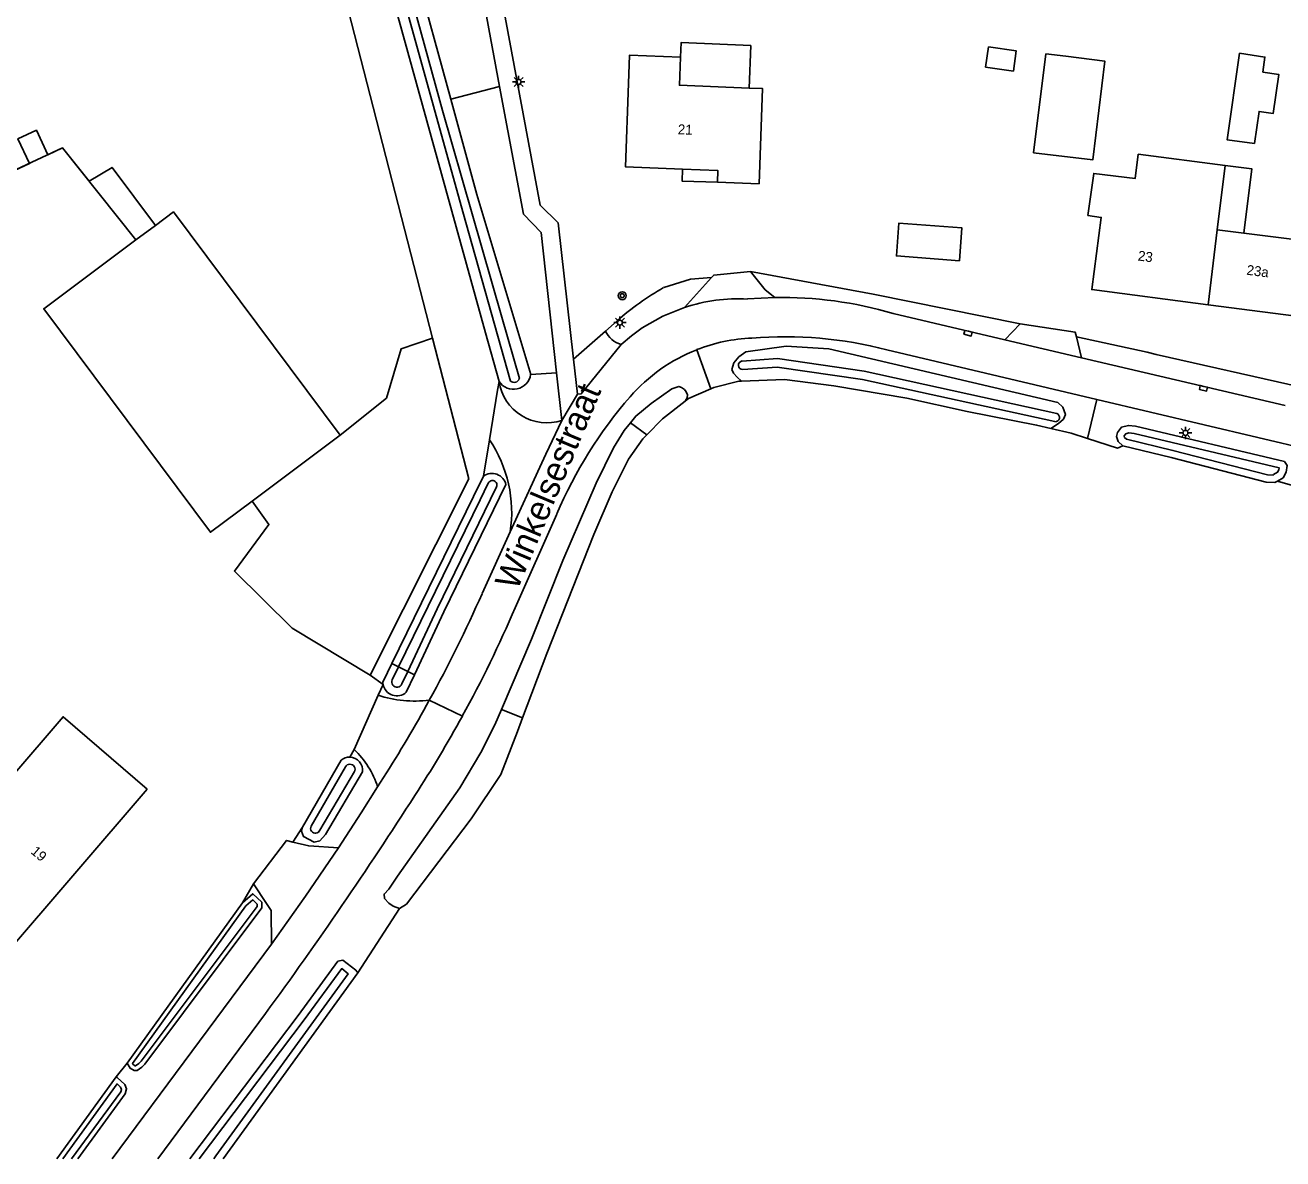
# Model space of a CAD drawing. Extents: x 140000 to 143000, y 403500 to 406000.
# Drawn here: x 140373.2 to 140499.7, y 403500 to 403614.1 of the extents above; entities that cross this region are included whole.
import ezdxf

# ---------------------------------------------------------------- set-up
doc = ezdxf.new("R2010")
doc.units = 0
for name, color, linetype in [('gg-afsc-erfafscheiding', 7, 'Continuous'), ('gg-afsc-hekwerk', 7, 'Continuous'), ('gg-anno-huisnummerreeks BGT', 7, 'Continuous'), ('gg-anno-openbare ruimte label', 7, 'Continuous'), ('gg-bbg-bijgebouw', 7, 'Continuous'), ('gg-bbg-hoofdgebouw', 7, 'Continuous'), ('gg-bbg-luifel en loopbrug', 7, 'Continuous'), ('gg-bbg-overig bouwwerk', 7, 'Continuous'), ('gg-bbg-tussenscheiding', 7, 'Continuous'), ('gg-knt-bronhoudergrens', 7, 'Continuous'), ('gg-knt-verharding', 7, 'Continuous'), ('gg-knt-verharding nz', 7, 'Continuous'), ('gg-kntw-bovenkant insteek waterloop', 7, 'Continuous'), ('gg-kntw-waterlijn', 7, 'Continuous'), ('gt-grn-groengrens', 7, 'Continuous'), ('gt-grn-groengrens NZ', 7, 'Continuous'), ('gt-grn-vlakafsluiter', 7, 'Continuous'), ('gt-grn-weggrens', 7, 'Continuous'), ('gt-symb-boom', 7, 'Continuous'), ('gt-symb-kolk', 7, 'Continuous'), ('gt-symb-lichtmast', 7, 'Continuous')]:
    doc.layers.add(name, color=color, linetype=linetype)

# ---------------------------------------------------------------- blocks, each defined once
blk = doc.blocks.new('gt0-LMAST')
at = {"layer": 'gt-symb-lichtmast'}
for p, q in [((-0.18, 0.17), (-0.45, 0.44)), ((-0.01, 0.25), (-0.01, 0.62)), ((0.17, 0.17), (0.44, 0.44)), ((-0.26, 0), (-0.63, 0)), ((-0.18, -0.18), (-0.45, -0.45)), ((-0.01, -0.25), (-0.01, -0.63)), ((0.44, -0.45), (0.17, -0.18)), ((0.24, 0), (0.62, 0))]:
    blk.add_line(p, q, dxfattribs=at)
blk.add_circle((-0.01, 0), 0.25, dxfattribs=at)
blk = doc.blocks.new('gt0-KOLK')
at = {"layer": 'gt-symb-kolk'}
blk.add_lwpolyline([(0, 0), (0.38, 0), (0.38, 0.4), (-0.37, 0.4), (-0.37, 0), (0, 0)], dxfattribs=at)
blk = doc.blocks.new('gt0-BOOM')
at = {"layer": 'gt-symb-boom'}
for radius in [0.4, 0.2]:
    blk.add_circle((0, 0), radius, dxfattribs=at)

msp = doc.modelspace()

# ---------------------------------------------------------------- linework, layer by layer
at = {"layer": 'gg-afsc-erfafscheiding'}
for p, q in [((140431.56, 403583.29), (140432.73, 403584.31)), ((140407.9, 403548.67), (140409.2, 403547.73)), ((140409.2, 403547.73), (140408.68, 403546.64)), ((140406.26, 403541.18), (140405.83, 403540.42)), ((140401.07, 403533.39), (140400.11, 403531.88)), ((140396.14, 403527.66), (140395.04, 403525.77)), ((140383.43, 403509.63), (140382.34, 403508.24))]:
    msp.add_line(p, q, dxfattribs=at)
for points in [[(140442.22, 403588.68), (140440.1, 403588.52), (140437.41, 403587.66)], [(140446.16, 403589.28), (140458.47, 403587.02), (140473.26, 403584.03)], [(140501.53, 403577.66), (140486.94, 403580.93), (140486.06, 403581.18), (140478.93, 403582.72)]]:
    msp.add_lwpolyline(points, dxfattribs=at)
msp.add_arc((140450.92, 403563.83), 27.4, 119.5448, 131.6023, dxfattribs=at)
at = {"layer": 'gg-afsc-hekwerk'}
msp.add_line((140483.05, 403571.5), (140480.06, 403572.48), dxfattribs=at)
for points in [[(140384.32, 403592.47), (140376.95, 403601.73), (140355.11, 403591.55), (140356.27, 403589.35)], [(140414.17, 403582.59), (140410.99, 403581.49), (140409.52, 403576.55), (140404.88, 403572.81)], [(140407.9, 403548.67), (140417.82, 403568.41), (140414.17, 403582.59)], [(140442.16, 403577.49), (140439.9, 403576.5), (140439.57, 403576.24)], [(140445.23, 403578.25), (140444.96, 403578.24), (140442.44, 403577.61), (140442.16, 403577.49)], [(140476.36, 403573.5), (140474.92, 403573.84), (140467.95, 403575.21), (140461.87, 403576.54), (140454.52, 403577.79), (140449.57, 403578.43), (140445.23, 403578.25)], [(140439.57, 403576.24), (140437.3, 403574.46), (140435.7, 403572.84), (140435.33, 403572.46), (140433.86, 403570.39), (140432.24, 403567.1), (140430.39, 403562.83), (140425.66, 403550.86), (140423.21, 403544.36), (140422.7, 403543.01)], [(140480.06, 403572.48), (140478.4, 403573.03), (140476.36, 403573.5)], [(140396.01, 403566.18), (140397.7, 403563.83), (140394.22, 403559.14), (140400.05, 403553.4), (140407.9, 403548.67)]]:
    msp.add_lwpolyline(points, dxfattribs=at)
at = {"layer": 'gg-bbg-bijgebouw'}
for p, q in [((140386.28, 403593.93), (140384.32, 403592.47)), ((140396.01, 403566.18), (140404.88, 403572.81))]:
    msp.add_line(p, q, dxfattribs=at)
for points in [[(140475.84, 403611.19), (140474.62, 403601.24), (140480.58, 403600.52), (140481.78, 403610.46), (140477.85, 403610.95), (140475.84, 403611.19)], [(140404.88, 403572.81), (140388.1, 403595.29), (140386.28, 403593.93)], [(140384.32, 403592.47), (140375.04, 403585.54), (140391.82, 403563.05), (140396.01, 403566.18)]]:
    msp.add_lwpolyline(points, dxfattribs=at)
at = {"layer": 'gg-bbg-hoofdgebouw'}
for q in [(140493.88, 403599.96), (140495.76, 403593.14)]:
    msp.add_line((140493.08, 403593.47), q, dxfattribs=at)
for points in [[(140439.11, 403610.86), (140433.96, 403611.05), (140433.86, 403608.21), (140433.57, 403599.81), (140439.31, 403599.58)], [(140446.01, 403607.75), (140438.99, 403608.02), (140439.11, 403610.86)], [(140446.01, 403607.75), (140447.36, 403607.7), (140447.01, 403598.11), (140442.81, 403598.26)], [(140493.88, 403599.96), (140485.15, 403601.08), (140484.83, 403598.64), (140480.68, 403599.15), (140480.09, 403594.93), (140481.42, 403594.73), (140480.47, 403587.47), (140492.18, 403585.94)], [(140439.31, 403599.58), (140442.86, 403599.44), (140442.81, 403598.26)], [(140492.18, 403585.94), (140503.1, 403584.51), (140504.08, 403592.11), (140495.76, 403593.14)], [(140385.46, 403537.21), (140376.99, 403544.49), (140366.44, 403532.19), (140368.31, 403530.59), (140364.3, 403525.91), (140367.1, 403523.5), (140370.89, 403520.24), (140385.46, 403537.21)]]:
    msp.add_lwpolyline(points, dxfattribs=at)
at = {"layer": 'gg-bbg-luifel en loopbrug'}
for points in [[(140446.01, 403607.75), (140446.17, 403612.02), (140439.18, 403612.33), (140439.11, 403610.86)], [(140493.88, 403599.96), (140496.56, 403599.62), (140495.76, 403593.14)], [(140439.31, 403599.58), (140439.26, 403598.39), (140442.81, 403598.26)]]:
    msp.add_lwpolyline(points, dxfattribs=at)
at = {"layer": 'gg-bbg-overig bouwwerk'}
for points in [[(140469.8, 403609.85), (140472.59, 403609.45), (140472.88, 403611.48), (140470.09, 403611.88), (140469.8, 403609.85)], [(140495.34, 403611.26), (140494.1, 403602.52), (140496.84, 403602.17), (140497.3, 403605.39), (140498.71, 403605.18), (140499.28, 403609.12), (140497.69, 403609.35), (140497.89, 403610.86), (140495.34, 403611.26)], [(140467.17, 403590.37), (140467.42, 403593.67), (140461.08, 403594.15), (140460.83, 403590.85), (140467.17, 403590.37)]]:
    msp.add_lwpolyline(points, dxfattribs=at)
at = {"layer": 'gg-bbg-tussenscheiding'}
msp.add_line((140492.18, 403585.94), (140493.08, 403593.47), dxfattribs=at)
at = {"layer": 'gg-knt-bronhoudergrens'}
for p, q in [((140502.08, 403567.36), (140499.15, 403568.2)), ((140406.65, 403518.71), (140410.83, 403525.18))]:
    msp.add_line(p, q, dxfattribs=at)
for points in [[(140356.27, 403589.35), (140355.11, 403591.55), (140373.6, 403600.17), (140372.45, 403602.64), (140374.31, 403603.5), (140375.46, 403601.04), (140376.95, 403601.73), (140379.63, 403598.36), (140381.93, 403599.76), (140386.28, 403593.93)], [(140439.57, 403576.24), (140439.9, 403576.5), (140442.16, 403577.49)], [(140442.16, 403577.49), (140442.44, 403577.61), (140444.96, 403578.24), (140445.23, 403578.25)], [(140480.06, 403572.48), (140478.4, 403573.03), (140476.36, 403573.5)], [(140480.06, 403572.48), (140483.05, 403571.5), (140483.59, 403571.74)]]:
    msp.add_lwpolyline(points, dxfattribs=at)
at = {"layer": 'gg-knt-verharding'}
for p, q in [((140439.51, 403585.68), (140442.22, 403588.68)), ((140471.74, 403582.42), (140460.49, 403585.05)), ((140471.74, 403582.42), (140473.26, 403584.03)), ((140428.35, 403580.45), (140431.56, 403583.29)), ((140479.44, 403580.61), (140478.93, 403582.72)), ((140459.86, 403581.41), (140480.99, 403576.41)), ((140428.75, 403576.95), (140428.35, 403580.45)), ((140499.92, 403575.82), (140479.44, 403580.61)), ((140427.17, 403574.3), (140426.64, 403579.09)), ((140428.75, 403576.95), (140427.17, 403574.3)), ((140480.99, 403576.41), (140502.99, 403571.2)), ((140422.48, 403555.45), (140426.67, 403564.88)), ((140421.98, 403563.08), (140419.14, 403556.87)), ((140406.26, 403541.18), (140408.68, 403546.64)), ((140381.93, 403500), (140397.96, 403521.61)), ((140386.52, 403500), (140397.34, 403514.62))]:
    msp.add_line(p, q, dxfattribs=at)
for points in [[(140406.1, 403674.88), (140407.67, 403655.99), (140419.56, 403619.22), (140419.42, 403615.9), (140420.91, 403607.91)], [(140428.35, 403580.45), (140426.79, 403594.18), (140424.99, 403595.96), (140421.18, 403616.33), (140421.45, 403619.53), (140409.47, 403656.48), (140408.2, 403671.5), (140411.12, 403673.65), (140421.06, 403674.9)], [(140420.91, 403607.91), (140423.3, 403595.07), (140425.07, 403593.22), (140426.64, 403579.09)], [(140446.16, 403589.28), (140442.44, 403588.92), (140442.22, 403588.68)], [(140448.58, 403586.67), (140447.62, 403587.43), (140446.16, 403589.28)], [(140439.51, 403585.68), (140437.31, 403584.8), (140435.26, 403583.62), (140434.16, 403582.83), (140433.13, 403581.95)], [(140473.26, 403584.03), (140478.81, 403583.17), (140478.93, 403582.72)], [(140419.89, 403572.36), (140420.71, 403577.33), (140420.85, 403578.21)], [(140407.9, 403548.67), (140400.05, 403553.4), (140394.22, 403559.14), (140397.7, 403563.83), (140396.01, 403566.18)], [(140408.63, 403537.42), (140406.99, 403534.82), (140404.69, 403531.31)], [(140400.11, 403531.88), (140399.47, 403532.04), (140396.14, 403527.66)], [(140404.69, 403531.31), (140401.7, 403531.48), (140400.11, 403531.88)], [(140397.96, 403521.61), (140397.92, 403524.99), (140397.44, 403525.71), (140396.14, 403527.66)]]:
    msp.add_lwpolyline(points, dxfattribs=at)
for centre, radius, start, end in [((140449.34, 403547.61), 39.07, 73.4147, 91.1163), ((140433.86, 403584.4), 2.56, 205.8661, 253.354), ((140446.97, 403565.5), 17.1, 92.2921, 111.3633), ((140449.59, 403541.58), 41.14, 75.5411, 94.6075), ((140446.97, 403565.5), 17.09, 111.3791, 139.1474), ((140425.66, 403578.92), 4.86, 188.4604, 288.1012), ((140467.62, 403547.51), 44.49, 139.0139, 157.0076), ((140409, 403565.03), 13.12, 351.4562, 33.9414), ((140290.11, 403614.04), 141.13, 331.2439, 336.1015), ((140309.19, 403603.93), 123.22, 331.1874, 336.8348), ((140412.36, 403557.97), 11.91, 251.9994, 277.0863), ((140309.2, 403603.91), 123.21, 326.873, 331.1932), ((140400.51, 403534.92), 8.5, 17.0887, 47.4029), ((140049.51, 403769.07), 430.97, 323.8141, 327.3521)]:
    msp.add_arc(centre, radius, start, end, dxfattribs=at)
at = {"layer": 'gg-knt-verharding nz'}
for p, q in [((140479.44, 403580.61), (140471.74, 403582.42)), ((140409.24, 403538.37), (140408.63, 403537.42))]:
    msp.add_line(p, q, dxfattribs=at)
for points in [[(140448.58, 403586.67), (140447.21, 403586.62), (140445.85, 403586.52)], [(140433.13, 403581.95), (140429.11, 403576.99), (140428.75, 403576.95)], [(140427.17, 403574.3), (140425.55, 403570.92), (140424.95, 403569.6), (140421.98, 403563.08)], [(140404.69, 403531.31), (140401.37, 403526.42), (140397.96, 403521.61)]]:
    msp.add_lwpolyline(points, dxfattribs=at)
for centre, radius, start, end in [((140444.92, 403569.13), 17.41, 86.9418, 108.1018), ((140289.84, 403614.18), 141.43, 327.5859, 331.2477)]:
    msp.add_arc(centre, radius, start, end, dxfattribs=at)
at = {"layer": 'gg-kntw-bovenkant insteek waterloop'}
for p, q in [((140410.07, 403549.85), (140409.18, 403548.03)), ((140411.51, 403546.95), (140412.33, 403548.7)), ((140401.07, 403533.39), (140404.96, 403540.12)), ((140395.04, 403525.77), (140383.43, 403509.63)), ((140393.09, 403500), (140406.65, 403518.71)), ((140376.37, 403500), (140382.34, 403508.24))]:
    msp.add_line(p, q, dxfattribs=at)
for points in [[(140420.85, 403578.21), (140419.47, 403583.11), (140410.65, 403615.1), (140404.44, 403637.32), (140400.95, 403650.31), (140399.75, 403655.87), (140397.36, 403674.15), (140397.48, 403675.34), (140397.93, 403676.05), (140398.38, 403676.52), (140398.92, 403676.79), (140399.36, 403676.66), (140399.71, 403676.32), (140402.3, 403656.1), (140403.18, 403651.75), (140408.57, 403633.77), (140416, 403606.64)], [(140416, 403606.64), (140418.63, 403597.03), (140424.03, 403578.92)], [(140445.23, 403578.25), (140444.79, 403578.65), (140444.45, 403579.04), (140444.27, 403579.42), (140444.46, 403580.1), (140444.96, 403580.69), (140445.66, 403581.22), (140449.74, 403581.79), (140454.01, 403581.52), (140477.05, 403576.12), (140477.57, 403575.62), (140477.82, 403574.91), (140477.63, 403574.43), (140477.13, 403573.98), (140476.36, 403573.5)], [(140439.57, 403576.24), (140439.77, 403576.59), (140439.8, 403576.89), (140439.67, 403577.17), (140439.49, 403577.41), (140439.2, 403577.61), (140438.93, 403577.72), (140438.22, 403577.48), (140436.14, 403575.99), (140434.6, 403574.73), (140434.06, 403574.07)], [(140445.23, 403578.25), (140449.57, 403578.43), (140454.52, 403577.79), (140461.87, 403576.54), (140467.95, 403575.21), (140474.92, 403573.84), (140476.36, 403573.5)], [(140439.57, 403576.24), (140437.3, 403574.46), (140435.7, 403572.84)], [(140434.06, 403574.07), (140433.44, 403573.3), (140432.35, 403571.54), (140430.63, 403567.98), (140427.26, 403560.2), (140424.11, 403552.29), (140421.09, 403545.23)], [(140483.59, 403571.74), (140483.14, 403572.17), (140482.95, 403572.67), (140483.05, 403573.09), (140483.45, 403573.62), (140484.16, 403573.8), (140484.88, 403573.71), (140499.85, 403570.17), (140500.13, 403569.78), (140500.02, 403569.09), (140499.73, 403568.54), (140499.15, 403568.2)], [(140435.7, 403572.84), (140435.33, 403572.46), (140433.86, 403570.39), (140432.24, 403567.1), (140430.39, 403562.83), (140425.66, 403550.86), (140423.21, 403544.36)], [(140483.59, 403571.74), (140488.46, 403570.56), (140498.03, 403568.09), (140498.9, 403568.06), (140499.15, 403568.2)], [(140410.07, 403549.85), (140418.28, 403566.63), (140419.28, 403568.68)], [(140412.33, 403548.7), (140415.29, 403555.04), (140421.54, 403567.84)], [(140421.09, 403545.23), (140420.42, 403543.68), (140419.02, 403540.88), (140416.89, 403537.32), (140410.62, 403528.45), (140409.76, 403527.13), (140409.29, 403526.64), (140409.34, 403526.2), (140409.76, 403525.73), (140410.21, 403525.44), (140410.83, 403525.18)], [(140423.21, 403544.36), (140422.7, 403543.01), (140421.02, 403538.67), (140418.05, 403534.22), (140411.54, 403525.64), (140410.83, 403525.18)], [(140407.12, 403538.95), (140403.4, 403532.63), (140402.81, 403532.01), (140402.24, 403531.88), (140401.18, 403532.43), (140400.97, 403532.98), (140401.07, 403533.39)], [(140395.04, 403525.77), (140396.08, 403526.68), (140396.97, 403525.83), (140396.98, 403525.25), (140385.2, 403509.53), (140384.92, 403509.23), (140384.43, 403508.9), (140384.14, 403508.9), (140383.73, 403509.12), (140383.43, 403509.63)], [(140389.74, 403500), (140400.65, 403514.44), (140404.64, 403519.89), (140405.15, 403520), (140406.44, 403518.97), (140406.65, 403518.71)], [(140378.46, 403500), (140383.24, 403506.53), (140383.38, 403507.03), (140383.19, 403507.48), (140382.45, 403508.19), (140382.34, 403508.24)]]:
    msp.add_lwpolyline(points, dxfattribs=at)
for centre, radius, start, end in [((140422.3, 403579.19), 1.75, 214.0663, 351.255), ((140420.14, 403567.53), 1.44, 12.3319, 126.867), ((140410.54, 403547.99), 1.37, 178.4515, 190.8507), ((140410.57, 403547.99), 1.4, 190.6305, 312.0387), ((140405.79, 403539.09), 1.33, 88.4634, 128.803), ((140405.8, 403539.08), 1.33, 354.23, 88.638)]:
    msp.add_arc(centre, radius, start, end, dxfattribs=at)
at = {"layer": 'gg-kntw-waterlijn'}
for p, q in [((140410.74, 403549.51), (140410.09, 403548.19)), ((140411.08, 403547.8), (140411.66, 403549.04)), ((140405.4, 403539.44), (140401.94, 403533.46)), ((140406.3, 403538.96), (140402.83, 403533.07))]:
    msp.add_line(p, q, dxfattribs=at)
for points in [[(140422.01, 403578.25), (140417.19, 403595.3), (140411.3, 403616.57), (140403.88, 403643.13), (140402.24, 403648.78), (140401.59, 403651.4), (140400.92, 403653.77), (140400.54, 403656.18), (140399.22, 403666.63), (140398.15, 403675.74), (140398.28, 403675.87), (140398.58, 403676.02), (140399.06, 403675.86), (140399.21, 403675.52), (140401.74, 403656.78), (140402, 403653.48), (140402.42, 403651.77), (140403.56, 403647.85), (140407.7, 403632.6), (140415.15, 403605.49), (140421.14, 403584.7), (140422.89, 403578.51)], [(140476.95, 403575.01), (140457.58, 403579.25), (140448.87, 403580.53), (140445.32, 403580.28)], [(140476.76, 403574.18), (140457.4, 403578.42), (140448.84, 403579.67), (140445.38, 403579.43)], [(140499.3, 403569.33), (140499.33, 403569.53), (140484.74, 403572.97), (140484.21, 403573.04), (140483.89, 403572.96), (140483.74, 403572.76), (140483.73, 403572.72), (140483.78, 403572.6), (140483.96, 403572.42), (140488.64, 403571.29), (140498.14, 403568.84), (140498.71, 403568.81), (140498.77, 403568.85), (140499.17, 403569.08), (140499.3, 403569.33)], [(140410.74, 403549.51), (140418.95, 403566.3), (140419.77, 403567.98)], [(140411.66, 403549.04), (140414.62, 403555.36), (140420.6, 403567.62)], [(140384.26, 403509.36), (140384.28, 403509.36), (140384.61, 403509.59), (140384.84, 403509.83), (140396.51, 403525.4), (140396.51, 403525.62), (140396.07, 403526.05), (140395.38, 403525.46), (140383.99, 403509.61), (140384.07, 403509.47), (140384.26, 403509.36)], [(140390.68, 403500), (140401.25, 403513.99), (140405.03, 403519.14), (140405.67, 403518.63), (140392.37, 403500.29), (140392.15, 403500)], [(140377.85, 403500), (140382.79, 403506.75), (140382.86, 403506.99), (140382.78, 403507.2), (140382.43, 403507.54), (140376.98, 403500)]]:
    msp.add_lwpolyline(points, dxfattribs=at)
for centre, radius, start, end in [((140445.35, 403579.86), 0.425, 94.061, 273.899), ((140422.36, 403578.67), 0.546, 230.0046, 343.2495), ((140476.8, 403574.6), 0.429, 265.2993, 69.9649), ((140420.19, 403567.8), 0.453, 335.5834, 157.8533), ((140410.58, 403547.98), 0.531, 156.1791, 340.2181), ((140405.85, 403539.2), 0.509, 331.4061, 151.741), ((140402.38, 403533.26), 0.484, 155.3943, 337.0894)]:
    msp.add_arc(centre, radius, start, end, dxfattribs=at)
at = {"layer": 'gt-grn-groengrens'}
for p, q in [((140420.91, 403607.91), (140416, 403606.64)), ((140426.64, 403579.09), (140424.03, 403578.92))]:
    msp.add_line(p, q, dxfattribs=at)
msp.add_lwpolyline([(140396.32, 403666.76), (140400.02, 403647.69), (140397.86, 403646.07), (140414.17, 403582.59), (140417.82, 403568.41), (140407.9, 403548.67)], dxfattribs=at)
at = {"layer": 'gt-grn-groengrens NZ'}
for p, q in [((140440.74, 403581.42), (140442.16, 403577.49)), ((140480.99, 403576.41), (140480.06, 403572.48)), ((140419.28, 403568.68), (140419.89, 403572.36))]:
    msp.add_line(p, q, dxfattribs=at)
at = {"layer": 'gt-grn-vlakafsluiter'}
for p, q in [((140434.06, 403574.07), (140435.7, 403572.84)), ((140410.74, 403549.51), (140410.07, 403549.85)), ((140410.74, 403549.51), (140411.66, 403549.04)), ((140411.66, 403549.04), (140412.33, 403548.7)), ((140423.21, 403544.36), (140421.09, 403545.23))]:
    msp.add_line(p, q, dxfattribs=at)
at = {"layer": 'gt-grn-weggrens'}
msp.add_line((140417.16, 403544.54), (140413.83, 403546.15), dxfattribs=at)

# ---------------------------------------------------------------- block references
at = {"layer": 'gt-symb-boom'}
msp.add_blockref('gt0-BOOM', (140433.24, 403586.85), dxfattribs=at)
at = {"layer": 'gt-symb-kolk', "rotation": 166.81908759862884}
for p in [(140468.08, 403583.27), (140491.76, 403577.73)]:
    msp.add_blockref('gt0-KOLK', p, dxfattribs=at)
at = {"layer": 'gt-symb-lichtmast'}
for p in [(140422.82, 403608.36), (140433.02, 403584.14), (140489.91, 403573.05)]:
    msp.add_blockref('gt0-LMAST', p, dxfattribs=at)

# ---------------------------------------------------------------- texts
at = {"layer": 'gg-anno-huisnummerreeks BGT'}
for s, rotation, p in [('21', 357.8, (140438.82, 403603.1)), ('23', 352.6, (140485.07, 403590.4)), ('23a', 352.6, (140496, 403588.97)), ('19', 319.4, (140373.67, 403530.81))]:
    msp.add_text(s, height=1, rotation=rotation, dxfattribs=at).set_placement(p)
at = {"layer": 'gg-anno-openbare ruimte label'}
msp.add_text('Winkelsestraat', height=2.5, rotation=67.2, dxfattribs=at).set_placement((140422.67, 403557.09))

doc.saveas('drawing.dxf')
